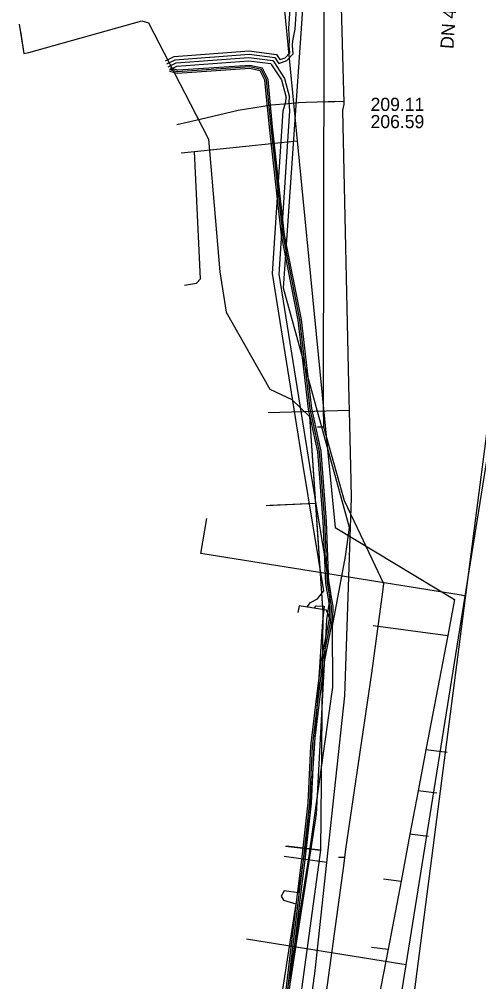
# Model space of a CAD drawing. Extents: x -596228 to -595156, y -1161235 to -1159373.
# Drawn here: x -595409.6 to -595381.6, y -1160832.9 to -1160774.3 of the extents above; entities that cross this region are included whole.
import ezdxf

# ---------------------------------------------------------------- set-up
doc = ezdxf.new("R2010")
doc.units = 0
for name, color, linetype in [('Vrstva 1', 7, 'Continuous'), ('Vrstva 12', 7, 'Continuous'), ('Vrstva 14', 7, 'Continuous'), ('Vrstva 16', 7, 'Continuous'), ('Vrstva 19', 7, 'Continuous'), ('Vrstva 4', 7, 'Continuous'), ('Vrstva 42', 7, 'Continuous'), ('Vrstva 44', 7, 'Continuous'), ('Vrstva 5', 7, 'Continuous'), ('Vrstva 58', 7, 'Continuous'), ('Vrstva 9', 7, 'Continuous')]:
    doc.layers.add(name, color=color, linetype=linetype)

msp = doc.modelspace()

# ---------------------------------------------------------------- linework, layer by layer
at = {"layer": 'Vrstva 1'}
for p, q in [((-595398.58, -1160790.09), (-595398.95, -1160782.32)), ((-595388.052, -1160811.215), (-595383.516, -1160811.822))]:
    msp.add_line(p, q, dxfattribs=at)
msp.add_lwpolyline([(-595399.56, -1160790.48), (-595398.83, -1160790.36), (-595398.58, -1160790.09)], dxfattribs=at)
at = {"layer": 'Vrstva 12'}
for p, q in [((-595391.57, -1160803.79), (-595394.58, -1160803.92)), ((-595391.27, -1160824.92), (-595393.45, -1160840.98)), ((-595393.39, -1160824.66), (-595391.27, -1160824.92))]:
    msp.add_line(p, q, dxfattribs=at)
for points in [[(-595391.73, -1160797.15), (-595393.53, -1160790.65), (-595392, -1160768.65), (-595392.17, -1160762.15), (-595393.27, -1160738.08), (-595395.42, -1160712.66)], [(-595409.55, -1160775.01), (-595409.34, -1160776.35), (-595409.04, -1160776.3), (-595402.15, -1160774.36), (-595401.75, -1160774.49), (-595399.2, -1160779.4), (-595398.1, -1160781.58), (-595397.4, -1160789.66), (-595397.01, -1160792.13), (-595394.35, -1160796.81), (-595393.01, -1160797.45), (-595391.93, -1160798.49), (-595391.57, -1160803.79)], [(-595390.53, -1160811.25), (-595389.74, -1160807.02), (-595389.49, -1160805.24), (-595391.73, -1160797.15)], [(-595391.57, -1160803.79), (-595391.12, -1160810.45), (-595391.27, -1160824.92)], [(-595390.53, -1160811.25), (-595390.9, -1160810.29), (-595392.57, -1160810.03), (-595392.64, -1160810.43)], [(-595396.61, -1160860.04), (-595396.17, -1160856.67), (-595395.33, -1160847.96), (-595393.5, -1160834.87), (-595391.96, -1160825.25), (-595391.27, -1160820.29), (-595390.52, -1160814.98), (-595390.53, -1160811.25)]]:
    msp.add_lwpolyline(points, dxfattribs=at)
at = {"layer": 'Vrstva 14'}
for points in [[(-595392.386, -1160880.463), (-595389, -1160860.26), (-595382.285, -1160808.426), (-595374.317, -1160746.92), (-595371.904, -1160743.843), (-595363.417, -1160733.399), (-595367.988, -1160714.713), (-595370.468, -1160704.744)], [(-595393.342, -1160876.76), (-595392.99, -1160875.24), (-595390.499, -1160859.689), (-595390.026, -1160856.737), (-595387.754, -1160842.558), (-595386.046, -1160831.895), (-595382.445, -1160809.421), (-595378.386, -1160784.054), (-595376.306, -1160771.081), (-595374.576, -1160760.301), (-595372.949, -1160750.146)], [(-595382.445, -1160809.421), (-595382.706, -1160809.379), (-595398.557, -1160806.84), (-595398.195, -1160804.693)], [(-595386.046, -1160831.895), (-595386.314, -1160831.852), (-595395.777, -1160830.336)]]:
    msp.add_lwpolyline(points, dxfattribs=at)
at = {"layer": 'Vrstva 16'}
for p, q in [((-595391.06, -1160799.13), (-595391.44, -1160799.13)), ((-595389.78, -1160825.36), (-595390.16, -1160825.35))]:
    msp.add_line(p, q, dxfattribs=at)
msp.add_lwpolyline([(-595391.76, -1160839.78), (-595389.85, -1160825.86), (-595389.78, -1160825.36), (-595389.72, -1160824.86), (-595388.14, -1160814.12), (-595387.51, -1160809.47), (-595387.4, -1160808.67), (-595389.01, -1160805.29), (-595389.8, -1160803.63), (-595391.06, -1160799.13), (-595391.08, -1160797.86), (-595391.014, -1160763.76)], dxfattribs=at)
at = {"layer": 'Vrstva 19'}
for p, q in [((-595389.5, -1160798.11), (-595394.46, -1160798.26)), ((-595390.88, -1160825.66), (-595393.48, -1160825.29))]:
    msp.add_line(p, q, dxfattribs=at)
for points in [[(-595389.404, -1160802.393), (-595389.5, -1160798.11), (-595389.515, -1160797.422), (-595389.9, -1160779.84), (-595389.83, -1160779.44), (-595389.83, -1160779.29), (-595389.84, -1160778.69), (-595390.29, -1160762.47), (-595390.66, -1160746.8), (-595390.803, -1160740.734), (-595391, -1160732.37), (-595392.01, -1160714.52)], [(-595389.83, -1160779.29), (-595390.39, -1160779.3), (-595390.79, -1160779.31), (-595392.13, -1160779.34), (-595392.59, -1160779.36), (-595393.26, -1160779.42), (-595394.25, -1160779.51), (-595396.28, -1160779.83), (-595398.59, -1160780.38), (-595400.01, -1160780.7), (-595400.02, -1160780.7)], [(-595396.06, -1160866.24), (-595395.51, -1160861.31), (-595394.5, -1160853.84), (-595392.81, -1160841.24), (-595391.6, -1160832.26), (-595390.88, -1160825.66), (-595389.78, -1160815.51), (-595389.38, -1160803.44), (-595389.404, -1160802.393)]]:
    msp.add_lwpolyline(points, dxfattribs=at)
at = {"layer": 'Vrstva 42'}
for points in [[(-595392.981, -1160775.879), (-595392.96, -1160775.586), (-595392.809, -1160774.871), (-595392.306, -1160767.127), (-595392.152, -1160764.854), (-595391.699, -1160758.146), (-595392.757, -1160748.803), (-595393.318, -1160743.424), (-595394.619, -1160718.319), (-595394.827, -1160714.688), (-595394.419, -1160714.064), (-595391.865, -1160712.692), (-595379.095, -1160708.846)], [(-595393.181, -1160775.883), (-595393.16, -1160775.573), (-595393.199, -1160774.839), (-595392.631, -1160766.275), (-595392.663, -1160766.21), (-595398.08, -1160766.397), (-595398.537, -1160766.407), (-595398.537, -1160766.207), (-595398.537, -1160766.007), (-595398.08, -1160765.997), (-595392.714, -1160765.797), (-595392.589, -1160765.626), (-595392.116, -1160758.279), (-595393.169, -1160748.862), (-595393.767, -1160743.464), (-595395.101, -1160718.222), (-595395.59, -1160714.754), (-595396.444, -1160714.03), (-595397.03, -1160713.242)], [(-595400.718, -1160776.813), (-595400.173, -1160776.541), (-595395.614, -1160776.197), (-595393.94, -1160776.413), (-595393.742, -1160776.716), (-595393.734, -1160776.727), (-595393.426, -1160776.614), (-595393.134, -1160776.314), (-595393.181, -1160775.883)], [(-595400.629, -1160776.992), (-595400.119, -1160776.737), (-595395.619, -1160776.398), (-595394.057, -1160776.6), (-595393.909, -1160776.825), (-595393.815, -1160776.97), (-595393.314, -1160776.786), (-595392.925, -1160776.386), (-595392.981, -1160775.879)], [(-595400.539, -1160777.171), (-595400.064, -1160776.934), (-595395.625, -1160776.599), (-595394.174, -1160776.787), (-595394.076, -1160776.935), (-595393.457, -1160777.879), (-595393.154, -1160779.028)], [(-595400.45, -1160777.35), (-595400.01, -1160777.13), (-595395.63, -1160776.8), (-595394.291, -1160776.973), (-595394.244, -1160777.045), (-595393.643, -1160777.961), (-595393.357, -1160779.045)], [(-595398.743, -1160867.114), (-595398.73, -1160867.021), (-595397.716, -1160867.162), (-595397.561, -1160866.474), (-595397.744, -1160865.424), (-595397.111, -1160860.772), (-595395.413, -1160847.915), (-595391.508, -1160822.721), (-595390.89, -1160810.876), (-595390.644, -1160809.221), (-595391.915, -1160801.462), (-595393.78, -1160789.797), (-595393.133, -1160779.844), (-595393.18, -1160779.33), (-595393.154, -1160779.028)], [(-595392.071, -1160810.071), (-595391.884, -1160809.812), (-595391.447, -1160809.594), (-595391.071, -1160809.112), (-595392.315, -1160801.462), (-595394.19, -1160789.764), (-595393.532, -1160779.854), (-595393.38, -1160779.313), (-595393.357, -1160779.045)], [(-595391.624, -1160810.138), (-595391.538, -1160810.018), (-595391.053, -1160810.05), (-595391.138, -1160810.975), (-595391.917, -1160822.701), (-595392.612, -1160827.51), (-595393.489, -1160827.39), (-595393.667, -1160827.719), (-595393.529, -1160827.949), (-595392.771, -1160828.189), (-595395.741, -1160847.225), (-595396.153, -1160847.432), (-595396.55, -1160847.727), (-595396.62, -1160847.918), (-595396.399, -1160847.899), (-595396.078, -1160847.875), (-595395.93, -1160847.764), (-595395.812, -1160847.881), (-595397.507, -1160860.72), (-595398.148, -1160865.432), (-595397.969, -1160866.464), (-595398.025, -1160866.715), (-595399.071, -1160866.57), (-595399.139, -1160867.058)]]:
    msp.add_lwpolyline(points, dxfattribs=at)
at = {"layer": 'Vrstva 44'}
for points in [[(-595393.639, -1160835.799), (-595392.709, -1160827.918), (-595392.399, -1160825.498), (-595392.01, -1160822.022), (-595391.85, -1160818.582), (-595391.489, -1160815.528), (-595391.199, -1160813.304), (-595390.72, -1160810.819), (-595390.7, -1160810.057), (-595390.95, -1160808.651), (-595391.1, -1160804.886), (-595391.419, -1160800.625), (-595391.989, -1160798.037), (-595392.629, -1160792.606), (-595393.649, -1160787.435), (-595394.38, -1160780.84), (-595394.648, -1160777.988), (-595394.938, -1160777.418), (-595395.577, -1160777.281), (-595399.98, -1160777.581), (-595400.476, -1160777.447)], [(-595393.441, -1160835.821), (-595392.511, -1160827.942), (-595392.201, -1160825.522), (-595391.81, -1160822.038), (-595391.65, -1160818.598), (-595391.291, -1160815.552), (-595391.001, -1160813.336), (-595390.52, -1160810.841), (-595390.5, -1160810.042), (-595390.75, -1160808.629), (-595390.9, -1160804.874), (-595391.221, -1160800.596), (-595391.791, -1160798.003), (-595392.431, -1160792.574), (-595393.451, -1160787.405), (-595394.181, -1160780.82), (-595394.452, -1160777.932), (-595394.802, -1160777.242), (-595395.563, -1160777.079), (-595399.96, -1160777.379), (-595400.424, -1160777.253)]]:
    msp.add_lwpolyline(points, dxfattribs=at)
at = {"layer": 'Vrstva 5'}
msp.add_line((-595399.753, -1160782.403), (-595398.95, -1160782.32), dxfattribs=at)
at = {"layer": 'Vrstva 58'}
for p, q in [((-595391.57, -1160803.79), (-595394.36, -1160803.91)), ((-595391.27, -1160824.92), (-595393.45, -1160840.98)), ((-595391.27, -1160824.92), (-595393.34, -1160824.67))]:
    msp.add_line(p, q, dxfattribs=at)
for points in [[(-595409.62, -1160774.57), (-595409.34, -1160776.35), (-595409.04, -1160776.3), (-595402.15, -1160774.36), (-595401.75, -1160774.49), (-595399.2, -1160779.4), (-595398.1, -1160781.58), (-595397.4, -1160789.66), (-595397.01, -1160792.13), (-595394.35, -1160796.81), (-595393.01, -1160797.45), (-595391.93, -1160798.49), (-595391.12, -1160810.45), (-595391.27, -1160824.92)], [(-595395.06, -1160850.45), (-595395.02, -1160849.63), (-595394.33, -1160842.9), (-595393.54, -1160835.81), (-595392.61, -1160827.93), (-595392.3, -1160825.51), (-595391.91, -1160822.03), (-595391.75, -1160818.59), (-595391.39, -1160815.54), (-595391.1, -1160813.32), (-595390.62, -1160810.83), (-595390.6, -1160810.05), (-595390.85, -1160808.64), (-595391, -1160804.88), (-595391.32, -1160800.61), (-595391.89, -1160798.02), (-595392.53, -1160792.59), (-595393.55, -1160787.42), (-595394.28, -1160780.83), (-595394.55, -1160777.96), (-595394.87, -1160777.33), (-595395.57, -1160777.18), (-595399.97, -1160777.48), (-595400.45, -1160777.35)]]:
    msp.add_lwpolyline(points, dxfattribs=at)
at = {"layer": 'Vrstva 9'}
for p, q in [((-595398.95, -1160782.32), (-595392.68, -1160781.67)), ((-595390.37, -1160805.25), (-595383.099, -1160809.629)), ((-595383.549, -1160818.955), (-595384.841, -1160818.789)), ((-595384.181, -1160821.445), (-595385.319, -1160821.299)), ((-595384.677, -1160824.073), (-595385.817, -1160823.927)), ((-595387.425, -1160826.654), (-595386.362, -1160826.791)), ((-595388.156, -1160830.825), (-595387.154, -1160830.954))]:
    msp.add_line(p, q, dxfattribs=at)
for points in [[(-595394.74, -1160760.61), (-595394.4, -1160764.1), (-595392.68, -1160781.67), (-595390.37, -1160805.25)], [(-595383.099, -1160809.629), (-595383.516, -1160811.822), (-595384.841, -1160818.789), (-595385.319, -1160821.299), (-595385.817, -1160823.927), (-595386.362, -1160826.791), (-595387.154, -1160830.954), (-595387.723, -1160833.966), (-595388.305, -1160837.027), (-595388.492, -1160838.021), (-595389.261, -1160842.076), (-595389.263, -1160842.086), (-595389.401, -1160842.814), (-595389.41, -1160842.864), (-595389.69, -1160844.34)]]:
    msp.add_lwpolyline(points, dxfattribs=at)

# ---------------------------------------------------------------- texts
at = {"layer": 'Vrstva 4'}
msp.add_text('DN 400 BET', height=0.8, rotation=86, dxfattribs=at).set_placement((-595383.171, -1160776.095))
for s, p in [('209.11', (-595388.215, -1160779.857)), ('206.59', (-595388.215, -1160780.907))]:
    msp.add_text(s, height=0.8, dxfattribs=at).set_placement(p)

doc.saveas('drawing.dxf')
